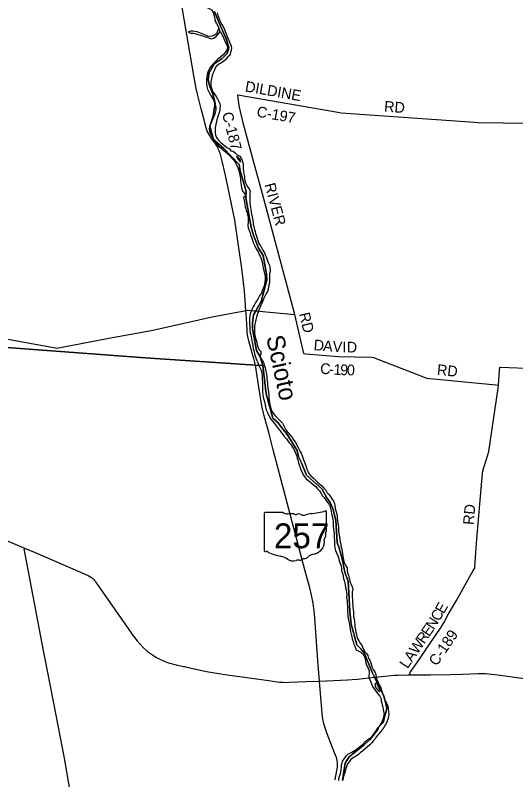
# Model space of a CAD drawing. Extents: x 1674899 to 2057726, y 653888 to 988278.
# Drawn here: x 1771738 to 1785762, y 843541 to 864966 of the extents above; entities that cross this region are included whole.
import ezdxf

# ---------------------------------------------------------------- set-up
doc = ezdxf.new("R2010")
doc.units = 0
for name, color, linetype in [('GM_X_County_Road', 7, 'Continuous'), ('GM_X_County_Road_Text', 7, 'Continuous'), ('GM_X_Major_River', 7, 'Continuous'), ('GM_X_Major_River_Text', 7, 'Continuous'), ('GM_X_State_Location', 7, 'Continuous'), ('GM_X_State_Route', 7, 'Continuous'), ('GM_X_State_Shield', 7, 'Continuous'), ('GM_X_Township', 7, 'Continuous')]:
    doc.layers.add(name, color=color, linetype=linetype)

msp = doc.modelspace()

# ---------------------------------------------------------------- linework, layer by layer
at = {"layer": 'GM_X_County_Road'}
for points in [[(1779569, 856584), (1779019, 858639), (1778669, 859959), (1778417, 860876), (1778136, 861918), (1778010, 862427), (1777970, 862741)], [(1777970, 862741), (1780778, 862248), (1780868, 862232), (1784609, 861971), (1784696, 861964), (1786106, 861939), (1786241, 861929)], [(1774515, 855940), (1775597, 856145), (1775681, 856161), (1777256, 856513), (1778103, 856674), (1778201, 856693), (1778256, 856697), (1778340, 856696), (1778464, 856683)], [(1778464, 856683), (1778481, 856682), (1778870, 856644), (1779569, 856584)], [(1779821, 855489), (1779569, 856584)], [(1771485, 855899), (1772805, 855652), (1772899, 855634), (1774513, 855940), (1774515, 855940)], [(1779821, 855489), (1779879, 855478), (1780796, 855402), (1781715, 855381), (1781774, 855378), (1783200, 854819), (1783259, 854796), (1785203, 854604), (1785283, 854596)], [(1782794, 846480), (1782798, 846516), (1782808, 846543), (1783085, 846950), (1783272, 847226), (1783653, 847787), (1783748, 847942), (1783883, 848187), (1784102, 848564), (1784433, 849156), (1784568, 849404), (1784612, 849472), (1784619, 849495), (1784625, 849639), (1784668, 850295), (1784833, 852121), (1784839, 852194), (1784977, 852649), (1785005, 852740), (1785271, 854516), (1785283, 854596), (1785312, 855017), (1785318, 855106), (1786321, 855070)], [(1773032, 837243), (1772998, 837442), (1772959, 837683), (1772924, 837925), (1772923, 837966), (1772930, 838064), (1773454, 841640), (1773504, 841940), (1773503, 842000), (1773497, 842064), (1773475, 842168), (1773363, 842728), (1773117, 844144), (1772881, 845349), (1772483, 847403), (1771993, 849965), (1771991, 849978), (1771991, 849991), (1771992, 850005), (1771995, 850019), (1771999, 850032)]]:
    msp.add_lwpolyline(points, dxfattribs=at)
at = {"layer": 'GM_X_Major_River'}
for p, q in [((1777481, 864498), (1777438, 864603)), ((1781289, 847181), (1781418, 847116))]:
    msp.add_line(p, q, dxfattribs=at)
for points in [[(1776801, 865827), (1776797, 865799), (1776795, 865749), (1776802, 865681), (1776806, 865611), (1776809, 865561), (1776823, 865493), (1776838, 865440), (1776878, 865374), (1776911, 865324), (1776971, 865277), (1777033, 865239), (1777098, 865198), (1777172, 865155), (1777236, 865115), (1777283, 865046), (1777305, 864976), (1777318, 864912), (1777333, 864846), (1777349, 864784), (1777373, 864733), (1777414, 864669), (1777438, 864603)], [(1777399, 865032), (1777414, 864961), (1777430, 864911), (1777457, 864839), (1777493, 864774), (1777530, 864710), (1777556, 864660), (1777589, 864593), (1777623, 864515), (1777642, 864461), (1777666, 864393), (1777689, 864338), (1777711, 864284), (1777744, 864214), (1777768, 864151), (1777787, 864099), (1777799, 864049), (1777791, 863987), (1777768, 863925), (1777751, 863851), (1777689, 863791), (1777638, 863726), (1777570, 863670), (1777500, 863620), (1777438, 863599), (1777371, 863531), (1777333, 863465), (1777308, 863406), (1777278, 863338), (1777255, 863274), (1777234, 863194), (1777220, 863112), (1777215, 863050), (1777219, 862977), (1777232, 862921), (1777258, 862867), (1777285, 862809), (1777321, 862758), (1777372, 862686), (1777408, 862621), (1777435, 862569), (1777461, 862517), (1777480, 862437), (1777474, 862363), (1777469, 862309), (1777453, 862238), (1777434, 862187), (1777414, 862119), (1777389, 862045), (1777375, 861979), (1777360, 861911), (1777346, 861857), (1777343, 861807), (1777337, 861741), (1777340, 861674), (1777346, 861610), (1777373, 861542), (1777425, 861471), (1777490, 861413), (1777550, 861352), (1777613, 861304), (1777669, 861257), (1777737, 861223), (1777774, 861164), (1777846, 861154), (1777904, 861107), (1777957, 861057), (1778027, 861014), (1778080, 860942), (1778102, 860871), (1778123, 860805), (1778127, 860741), (1778128, 860673), (1778135, 860593), (1778147, 860518), (1778158, 860448), (1778164, 860388), (1778171, 860338), (1778193, 860266), (1778218, 860213), (1778256, 860153), (1778303, 860087), (1778321, 860016), (1778314, 859958), (1778312, 859894), (1778309, 859838)], [(1777438, 864603), (1777376, 864451), (1777322, 864411), (1777256, 864377), (1777190, 864372), (1777136, 864382), (1777070, 864410), (1777018, 864427), (1776956, 864455), (1776886, 864481), (1776834, 864498), (1776771, 864512), (1776709, 864524), (1776649, 864522), (1776587, 864491), (1776654, 864468), (1776728, 864462), (1776780, 864454), (1776850, 864431), (1776918, 864413), (1776996, 864389), (1777060, 864364), (1777112, 864350), (1777163, 864330), (1777227, 864305), (1777295, 864323), (1777372, 864375), (1777481, 864498)], [(1777481, 864498), (1777504, 864466), (1777542, 864402), (1777573, 864337), (1777605, 864271), (1777630, 864205), (1777666, 864138), (1777681, 864070), (1777667, 864000), (1777616, 863926), (1777564, 863862), (1777491, 863797), (1777425, 863743), (1777374, 863702), (1777308, 863636), (1777251, 863572), (1777195, 863507), (1777160, 863441), (1777138, 863373), (1777117, 863309), (1777105, 863237), (1777098, 863171), (1777096, 863101), (1777101, 863032), (1777109, 862970), (1777124, 862898), (1777154, 862836), (1777189, 862765), (1777226, 862699), (1777272, 862628), (1777301, 862566), (1777323, 862498), (1777346, 862434), (1777358, 862363), (1777355, 862313), (1777343, 862245), (1777330, 862181), (1777294, 862111), (1777261, 862042), (1777233, 861978), (1777208, 861912), (1777184, 861840), (1777175, 861776), (1777185, 861710), (1777210, 861643), (1777247, 861565), (1777281, 861515), (1777325, 861450), (1777370, 861374), (1777427, 861309), (1777497, 861251), (1777560, 861194), (1777628, 861137), (1777699, 861079), (1777763, 861020), (1777818, 860954), (1777876, 860893), (1777915, 860825), (1777949, 860756), (1777976, 860688), (1778006, 860620), (1778023, 860551), (1778035, 860487), (1778042, 860437), (1778048, 860385), (1778049, 860335), (1778059, 860275), (1778066, 860209), (1778076, 860142), (1778083, 860092), (1778115, 860028), (1778174, 859965), (1778186, 859897), (1778136, 859859), (1778149, 859779), (1778157, 859725), (1778168, 859673), (1778184, 859601), (1778195, 859548), (1778211, 859492), (1778236, 859426), (1778250, 859376), (1778265, 859300), (1778263, 859247), (1778260, 859189), (1778259, 859063), (1778267, 859007), (1778294, 858937), (1778318, 858868), (1778331, 858816), (1778355, 858746), (1778382, 858662), (1778405, 858597), (1778439, 858527), (1778470, 858459), (1778506, 858396), (1778545, 858338), (1778577, 858265), (1778604, 858213), (1778628, 858145), (1778649, 858083)], [(1777933, 861011), (1777968, 860953), (1778040, 860862), (1778060, 860864)], [(1778060, 860864), (1778040, 860924), (1778004, 860962), (1777963, 861001), (1777933, 861011)], [(1778309, 859838), (1778307, 859768), (1778308, 859700), (1778320, 859628), (1778327, 859576), (1778337, 859523), (1778350, 859445), (1778360, 859393), (1778375, 859331), (1778383, 859275), (1778396, 859218), (1778400, 859164), (1778407, 859100), (1778419, 859034), (1778440, 858964), (1778456, 858909), (1778473, 858853), (1778489, 858803), (1778505, 858747), (1778522, 858685), (1778546, 858622), (1778567, 858572), (1778613, 858500), (1778644, 858441), (1778676, 858381), (1778719, 858310), (1778745, 858256), (1778768, 858196), (1778792, 858138), (1778819, 858057), (1778852, 857983), (1778876, 857909), (1778881, 857836), (1778879, 857784), (1778864, 857732), (1778864, 857680), (1778865, 857606), (1778865, 857556), (1778862, 857480), (1778852, 857430), (1778834, 857360), (1778825, 857282), (1778802, 857226), (1778764, 857166), (1778733, 857092), (1778701, 857034), (1778683, 856980), (1778644, 856901), (1778623, 856841), (1778599, 856783), (1778569, 856729), (1778550, 856675), (1778536, 856617)], [(1778649, 858083), (1778665, 858004), (1778676, 857938), (1778684, 857882), (1778701, 857814), (1778715, 857764), (1778732, 857691), (1778738, 857637), (1778739, 857565), (1778733, 857493), (1778726, 857443), (1778712, 857377), (1778687, 857311), (1778657, 857239), (1778636, 857175), (1778584, 857101), (1778541, 857032), (1778508, 856966), (1778470, 856914), (1778432, 856844), (1778407, 856792), (1778371, 856722), (1778348, 856660), (1778324, 856594), (1778309, 856538), (1778305, 856472), (1778306, 856418), (1778305, 856308), (1778307, 856246), (1778312, 856180), (1778312, 856130), (1778321, 856068), (1778335, 856007), (1778347, 855953), (1778354, 855901), (1778364, 855841), (1778385, 855763)], [(1778536, 856617), (1778528, 856623), (1778515, 856559), (1778497, 856501), (1778480, 856431), (1778470, 856379), (1778449, 856305), (1778445, 856243), (1778440, 856189), (1778442, 856119), (1778441, 856055), (1778451, 855986), (1778470, 855920), (1778486, 855862), (1778503, 855798), (1778521, 855727), (1778534, 855675), (1778562, 855603), (1778621, 855542), (1778621, 855472), (1778596, 855420), (1778622, 855350), (1778667, 855288), (1778699, 855219), (1778716, 855161), (1778732, 855111), (1778747, 855051), (1778763, 854986), (1778776, 854910), (1778784, 854846), (1778789, 854782), (1778802, 854655), (1778810, 854589), (1778817, 854533), (1778823, 854471), (1778830, 854399), (1778841, 854303), (1778847, 854232), (1778852, 854174), (1778862, 854116), (1778869, 854060), (1778891, 853978), (1778908, 853915), (1778944, 853843), (1778989, 853779), (1779041, 853724), (1779098, 853662), (1779154, 853607), (1779223, 853532), (1779255, 853482), (1779322, 853345), (1779379, 853271), (1779444, 853200), (1779496, 853132), (1779537, 853065), (1779587, 852999), (1779630, 852914), (1779668, 852848), (1779691, 852798), (1779723, 852743), (1779748, 852691), (1779778, 852617), (1779799, 852562), (1779817, 852510), (1779844, 852442), (1779864, 852391), (1779891, 852313), (1779913, 852245), (1779936, 852191), (1779966, 852128), (1780017, 852060), (1780085, 851999), (1780150, 851934), (1780202, 851892), (1780277, 851821), (1780329, 851779), (1780384, 851714), (1780438, 851658), (1780481, 851585), (1780525, 851533), (1780580, 851462), (1780610, 851410), (1780657, 851346), (1780683, 851281), (1780694, 851231), (1780704, 851163), (1780713, 851109), (1780733, 851050), (1780756, 850942), (1780760, 850860), (1780767, 850808), (1780786, 850671), (1780796, 850617), (1780799, 850563), (1780799, 850511), (1780802, 850457), (1780810, 850405), (1780823, 850340), (1780837, 850270), (1780844, 850204), (1780858, 850128)], [(1778385, 855763), (1778385, 855769), (1778399, 855702), (1778408, 855628), (1778423, 855568), (1778441, 855488), (1778454, 855437), (1778478, 855365), (1778501, 855305), (1778531, 855231), (1778550, 855178), (1778586, 855112), (1778619, 855040), (1778637, 854989), (1778650, 854923), (1778654, 854871), (1778655, 854803), (1778659, 854749), (1778662, 854691), (1778668, 854620), (1778667, 854482), (1778668, 854412), (1778674, 854334), (1778681, 854266), (1778703, 854197), (1778728, 854107), (1778741, 854049), (1778753, 853979), (1778772, 853908), (1778806, 853832), (1778865, 853711), (1778904, 853647), (1778946, 853593), (1778985, 853542), (1779039, 853476), (1779094, 853397), (1779159, 853316), (1779199, 853266), (1779242, 853206), (1779286, 853155), (1779340, 853091), (1779377, 853038), (1779417, 852986), (1779456, 852932), (1779502, 852863), (1779535, 852811), (1779575, 852746), (1779598, 852678), (1779616, 852628), (1779639, 852551), (1779653, 852497), (1779672, 852425), (1779692, 852365), (1779717, 852294), (1779741, 852230), (1779774, 852160), (1779794, 852103), (1779829, 852045), (1779891, 851975), (1779956, 851926), (1780022, 851869), (1780095, 851805), (1780163, 851756), (1780208, 851696), (1780260, 851633), (1780309, 851561), (1780351, 851502), (1780394, 851450), (1780444, 851373), (1780497, 851305), (1780547, 851242), (1780560, 851186), (1780578, 851120), (1780589, 851062), (1780603, 851005), (1780612, 850951), (1780626, 850895), (1780637, 850833), (1780643, 850779), (1780646, 850702), (1780650, 850630), (1780657, 850572), (1780669, 850504), (1780674, 850452), (1780676, 850380), (1780679, 850322), (1780683, 850241), (1780684, 850173), (1780688, 850107), (1780693, 850037), (1780711, 849969), (1780744, 849896), (1780775, 849814), (1780793, 849764), (1780807, 849713), (1780824, 849649), (1780855, 849581), (1780869, 849529), (1780877, 849470), (1780884, 849414), (1780892, 849364)], [(1780858, 850128), (1780869, 850062), (1780885, 849999), (1780896, 849933), (1780912, 849869), (1780921, 849805), (1780929, 849749), (1780948, 849660), (1780966, 849606), (1780995, 849554), (1781035, 849477), (1781038, 849421), (1781052, 849341), (1781077, 849271), (1781087, 849220), (1781100, 849160), (1781118, 849108), (1781133, 849046), (1781157, 848995), (1781184, 848929), (1781194, 848873), (1781181, 848805), (1781179, 848737), (1781180, 848667), (1781184, 848592), (1781191, 848520), (1781198, 848434), (1781200, 848368), (1781205, 848312), (1781215, 848246), (1781214, 848177), (1781220, 848115), (1781237, 848047), (1781247, 847977), (1781256, 847885), (1781258, 847830), (1781267, 847780), (1781275, 847728), (1781284, 847676), (1781296, 847612), (1781314, 847558), (1781339, 847483), (1781363, 847431), (1781392, 847379), (1781448, 847312), (1781473, 847252), (1781503, 847193), (1781528, 847139), (1781578, 847077), (1781615, 847018), (1781635, 846950), (1781672, 846888), (1781702, 846819), (1781721, 846755), (1781739, 846687), (1781764, 846628), (1781816, 846560), (1781839, 846489), (1781855, 846417), (1781872, 846351), (1781896, 846281), (1781933, 846210), (1781970, 846142), (1781996, 846075), (1782031, 845963), (1782043, 845913), (1782062, 845861), (1782088, 845790), (1782111, 845734), (1782143, 845682), (1782176, 845613), (1782188, 845535), (1782195, 845457), (1782204, 845379), (1782198, 845320), (1782192, 845270), (1782173, 845206), (1782149, 845152), (1782104, 845067), (1782070, 845005), (1782031, 844953), (1781973, 844879), (1781930, 844826), (1781858, 844756), (1781827, 844690), (1781771, 844632), (1781737, 844581), (1781676, 844523), (1781610, 844461), (1781551, 844412), (1781475, 844348), (1781406, 844291), (1781352, 844243), (1781290, 844205), (1781214, 844160), (1781143, 844104), (1781093, 844044), (1781052, 843989), (1781030, 843929), (1781001, 843855), (1780981, 843785)], [(1780892, 849364), (1780913, 849298), (1780931, 849232), (1780940, 849179), (1780950, 849127), (1780971, 849053), (1780979, 849001), (1780994, 848921), (1781008, 848862), (1781019, 848788), (1781025, 848720), (1781024, 848658), (1781030, 848584), (1781035, 848532), (1781043, 848471), (1781048, 848419), (1781052, 848365), (1781051, 848293), (1781051, 848241), (1781054, 848171), (1781062, 848117), (1781070, 848066), (1781077, 848008), (1781091, 847940), (1781100, 847880), (1781110, 847816), (1781133, 847699), (1781148, 847619), (1781168, 847549), (1781183, 847486), (1781206, 847412), (1781228, 847338), (1781251, 847282), (1781269, 847231), (1781289, 847181)], [(1781418, 847116), (1781476, 847059), (1781511, 847009), (1781535, 846959), (1781554, 846884), (1781558, 846808), (1781581, 846756), (1781607, 846704), (1781636, 846641), (1781656, 846579), (1781655, 846513), (1781645, 846453), (1781643, 846399), (1781684, 846332), (1781706, 846278), (1781723, 846226), (1781751, 846156), (1781796, 846085), (1781842, 846019), (1781895, 845946), (1781952, 845879), (1781990, 845811), (1781993, 845755), (1782009, 845685), (1782021, 845634), (1782034, 845574), (1782051, 845502), (1782067, 845420), (1782072, 845366), (1782058, 845308), (1782044, 845254), (1782019, 845186), (1781983, 845112), (1781938, 845044), (1781906, 844978), (1781875, 844926), (1781829, 844862), (1781780, 844793), (1781720, 844725), (1781645, 844677), (1781591, 844638), (1781525, 844582), (1781478, 844528), (1781414, 844473), (1781362, 844437), (1781291, 844376), (1781215, 844330), (1781165, 844306), (1781100, 844273), (1781048, 844245), (1780998, 844199), (1780941, 844130), (1780903, 844060), (1780888, 844006), (1780874, 843946), (1780868, 843894), (1780863, 843820), (1780853, 843754), (1780840, 843702), (1780810, 843634), (1780797, 843570), (1780797, 843520)], [(1781849, 846259), (1781815, 846219), (1781842, 846113), (1781904, 846040), (1781955, 846014), (1781968, 846070)], [(1781968, 846070), (1781918, 846138), (1781877, 846227), (1781849, 846259)], [(1780981, 843785), (1780960, 843719), (1780946, 843667), (1780925, 843595), (1780917, 843527)]]:
    msp.add_lwpolyline(points, dxfattribs=at)
at = {"layer": 'GM_X_State_Route'}
for points in [[(1780260, 846299), (1780214, 846871), (1780156, 847683), (1780119, 848192), (1780103, 848341), (1780082, 848490), (1780037, 848711), (1779990, 848921), (1779866, 849386), (1779314, 851479), (1778967, 852787), (1778849, 853232), (1778732, 853677), (1778659, 853968), (1778625, 854134), (1778535, 854732), (1778466, 855163), (1778422, 855348), (1778404, 855403), (1778338, 855632), (1778279, 855845), (1778264, 855913), (1778254, 855963), (1778240, 856063), (1778232, 856164), (1778207, 856610), (1778201, 856693), (1778158, 857245), (1778089, 857871), (1777889, 859222), (1777685, 860217), (1777620, 860525), (1777532, 860880), (1777486, 861060), (1777476, 861098), (1777464, 861135), (1777451, 861171), (1777436, 861207), (1777419, 861242), (1777383, 861311), (1777355, 861355), (1777221, 861539), (1777176, 861609), (1777119, 861721), (1777075, 861838), (1777027, 862032), (1776950, 862347), (1776840, 862758), (1776807, 862917), (1776749, 863221), (1776467, 864856), (1776332, 865707)], [(1770221, 850789), (1771999, 850032), (1772292, 849906), (1773777, 849265), (1773831, 849237), (1773877, 849206), (1773898, 849188), (1773937, 849150), (1773955, 849129), (1773972, 849107), (1773988, 849084), (1774185, 848807), (1774812, 847908), (1774968, 847684)], [(1774968, 847684), (1775017, 847613), (1775152, 847432), (1775319, 847250), (1775446, 847139), (1775582, 847039), (1775677, 846979), (1775773, 846927), (1775925, 846858), (1776029, 846819), (1776243, 846761), (1776454, 846715), (1776476, 846710)], [(1776476, 846710), (1776545, 846695), (1777099, 846577), (1777213, 846553), (1777679, 846483), (1778305, 846395), (1778834, 846323), (1779138, 846279), (1779232, 846271), (1779274, 846270), (1779424, 846274), (1779888, 846291), (1780260, 846299)], [(1782747, 846479), (1782794, 846480), (1783183, 846484), (1783377, 846485), (1783923, 846492), (1784269, 846503), (1784713, 846520), (1784920, 846517), (1785189, 846487), (1785532, 846441), (1785928, 846388), (1786488, 846310), (1787292, 846217), (1788027, 846133), (1788780, 846042), (1789296, 845980), (1789805, 845926), (1790403, 845872), (1791058, 845819), (1791646, 845786), (1792283, 845741), (1792907, 845707), (1794165, 845645)], [(1780260, 846299), (1780260, 846299), (1781047, 846338), (1781176, 846347), (1781331, 846363), (1781806, 846413), (1782009, 846435), (1782350, 846472), (1782467, 846475), (1782747, 846479)], [(1780704, 843535), (1780710, 843602), (1780766, 843894), (1780771, 843954), (1780769, 844015), (1780761, 844075), (1780737, 844162), (1780688, 844296), (1780481, 844827), (1780394, 845075), (1780375, 845141), (1780363, 845204), (1780347, 845305), (1780320, 845620), (1780260, 846299)]]:
    msp.add_lwpolyline(points, dxfattribs=at)
at = {"layer": 'GM_X_State_Shield'}
for p, q in [((1778717, 851011), (1778717, 849955)), ((1779244, 851029), (1778734, 851029)), ((1780457, 850503), (1780457, 851056)), ((1780457, 850503), (1780457, 850503))]:
    msp.add_line(p, q, dxfattribs=at)
for centre, major_axis, start_param, end_param in [((1778737, 851014), (20.2, 0), 1.712693, 3.28349), ((1779365, 851152), (196, 0), 4.042523, 4.731795), ((1779837, 852470), (1845, 0), 4.814394, 5.042369), ((1780438, 851058), (19.4, 0), 6.141152, 7.989035), ((1779430, 850436), (702, 0), 1.404758, 1.657858), ((1779589, 851019), (56.4, 0), 3.836095, 5.185415), ((1779672, 850897), (117, 0), 0.950623, 2.079405), ((1779823, 851064), (141, 0), 4.081561, 5.145723), ((1780073, 850707), (371, 0), 1.699011, 2.107814), ((1780453, 850462), (30, 0), 1.883978, 3.671073), ((1780262, 850392), (180, 0), 5.934695, 6.695948), ((1780436, 850501), (20.7, 0), 5.05454, 6.418171), ((1779941, 850201), (462, 0), 5.101752, 6.440018), ((1780527, 850272), (131, 0), 2.387724, 3.262537), ((1778737, 849952), (20.3, 0), 3.00124, 4.508301), ((1778740, 850060), (155, 0), 4.665946, 4.897461), ((1778772, 849894), (56, 0), 0.519207, 1.627899), ((1779478, 850843), (1333, 0), 4.195997, 4.488961), ((1779081, 849480), (417, 0), 0.823519, 1.323587), ((1779532, 849888), (265, 0), 4.026481, 4.996735), ((1779704, 849809), (141, 0), 4.691044, 5.507374), ((1779832, 849707), (39.7, 0), 1.147584, 2.315152), ((1779815, 849852), (149, 0), 4.937069, 5.64225), ((1780135, 849658), (253, 0), 1.647645, 2.488434), ((1779685, 849523), (217, 0), 1.495662, 1.94098)]:
    msp.add_ellipse(centre, major_axis=major_axis, ratio=0.8, start_param=start_param, end_param=end_param, dxfattribs=at)
at = {"layer": 'GM_X_Township'}
for points in [[(1777319, 865072), (1777430, 864796), (1777660, 864284), (1777723, 864054), (1777673, 863892), (1777527, 863741), (1777325, 863614), (1777170, 863351), (1777146, 863168), (1777172, 863030), (1777271, 862751), (1777344, 862501), (1777288, 862139), (1777189, 861855), (1777295, 861489), (1777585, 861235), (1778010, 860785), (1778036, 860617), (1778212, 860031), (1778195, 859863), (1778284, 859383), (1778344, 859030), (1778417, 858800), (1778551, 858440), (1778686, 858229), (1778777, 857706), (1778790, 857538), (1778631, 856948), (1778481, 856682), (1778415, 856566), (1778385, 856340), (1778390, 856177), (1778502, 855569), (1778601, 855389), (1778678, 855150), (1778466, 855163), (1775377, 855361), (1769242, 855826)], [(1780907, 843520), (1780980, 844003), (1781094, 844181), (1781518, 844515), (1781682, 844666), (1781918, 845013), (1782045, 845142), (1782155, 845534), (1782125, 845674), (1782062, 845883), (1781806, 846413), (1781752, 846525), (1781519, 847094), (1781420, 847210), (1781308, 847324), (1781148, 847901), (1781109, 848257), (1781090, 848776), (1781068, 849092), (1780971, 849357), (1780904, 849691), (1780816, 850027), (1780762, 850186), (1780725, 850820), (1780641, 851138), (1780564, 851310), (1780471, 851440), (1780333, 851692), (1779900, 852077), (1779756, 852426), (1779678, 852587), (1779637, 852766), (1779349, 853231), (1779232, 853362), (1779109, 853545), (1778954, 853677), (1778765, 854353), (1778678, 855150), (1778601, 855389), (1778502, 855569), (1778390, 856177), (1778385, 856340), (1778415, 856566), (1778481, 856682), (1778631, 856948), (1778790, 857538), (1778777, 857706), (1778686, 858229), (1778551, 858440), (1778417, 858800), (1778344, 859030), (1778284, 859383), (1778195, 859863), (1778212, 860031), (1778036, 860617), (1778010, 860785), (1777585, 861235), (1777295, 861489), (1777189, 861855), (1777288, 862139), (1777344, 862501), (1777271, 862751), (1777172, 863030), (1777146, 863168), (1777170, 863351), (1777325, 863614), (1777527, 863741), (1777673, 863892), (1777723, 864054), (1777660, 864284), (1777430, 864796), (1777319, 865072)], [(1769242, 855826), (1775377, 855361), (1778466, 855163), (1778678, 855150), (1778765, 854353), (1778954, 853677), (1779109, 853545), (1779232, 853362), (1779349, 853231), (1779637, 852766), (1779678, 852587), (1779756, 852426), (1779900, 852077), (1780333, 851692), (1780471, 851440), (1780564, 851310), (1780641, 851138), (1780725, 850820), (1780762, 850186), (1780816, 850027), (1780904, 849691), (1780971, 849357), (1781068, 849092), (1781090, 848776), (1781109, 848257), (1781148, 847901), (1781308, 847324), (1781420, 847210), (1781519, 847094), (1781752, 846525), (1781806, 846413), (1782062, 845883), (1782125, 845674), (1782155, 845534), (1782045, 845142), (1781918, 845013), (1781682, 844666), (1781518, 844515), (1781094, 844181), (1780980, 844003), (1780907, 843520)]]:
    msp.add_lwpolyline(points, dxfattribs=at)

# ---------------------------------------------------------------- texts
at = {"layer": 'GM_X_County_Road_Text'}
for s, rotation, p in [('DILDINE', 349.9524, (1778161, 862835)), ('C-197', 349.9922, (1778486, 862128)), ('RD', 355.5641, (1782066, 862269)), ('C-187', 284.4351, (1777529, 862213)), ('RIVER', 285.0351, (1778722, 860223)), ('RD', 283.4376, (1779690, 856601)), ('D', 355.0579, (1780091, 855582)), ('A', 355.1678, (1780355, 855559)), ('V', 356.655, (1780627, 855536)), ('I', 358.3653, (1780900, 855521)), ('D', 358.9574, (1781026, 855517)), ('C', 355.3582, (1780272, 854923)), ('1', 356.8855, (1780649, 854894)), ('9', 358.0643, (1780840, 854883)), ('0', 358.7849, (1781029, 854877)), ('RD', 354.584, (1783546, 854887)), ('-', 355.904, (1780520, 854903)), ('RD', 85.0302, (1784584, 850674)), ('E', 59.8094, (1783741, 848170)), ('C', 59.5456, (1783615, 847957)), ('N', 57.6172, (1783468, 847724)), ('E', 56.0097, (1783338, 847530)), ('R', 55.8341, (1783199, 847326)), ('C-189', 55.7837, (1783549, 846708)), ('W', 55.8342, (1783003, 847038)), ('A', 55.8379, (1782855, 846820)), ('L', 55.8345, (1782729, 846634))]:
    msp.add_text(s, height=300, rotation=rotation, dxfattribs=at).set_placement(p)
at = {"layer": 'GM_X_Major_River_Text'}
msp.add_text('Scioto', height=500, rotation=282.29, dxfattribs=at).set_placement((1778766, 855945))
at = {"layer": 'GM_X_State_Location'}
for s in ['s', 'r']:
    msp.add_text(s, height=1, dxfattribs=at).set_placement((1779567, 850413))
msp.add_text('257', height=1, rotation=0, dxfattribs=at).set_placement((1779214, 850340))
at = {"layer": 'GM_X_State_Shield'}
msp.add_text('257', height=696.1, dxfattribs=at).set_placement((1778985, 850029))

doc.saveas('drawing.dxf')
